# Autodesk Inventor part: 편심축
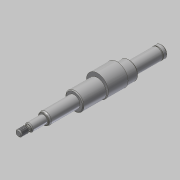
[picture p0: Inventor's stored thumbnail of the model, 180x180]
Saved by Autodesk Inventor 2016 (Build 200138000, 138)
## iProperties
Created: 2015-09
Part Number: 편심축
Material: 강철, 연강
Document SubType Name: Modeling
Designer: mduedu
Density: 1 g/cm^3
Appearance: 강철
Author: mduedu
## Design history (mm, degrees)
sketch "스케치1"
  geometry: L1 (-91, 0)-(91, 0); L2 (-91, 0)-(-91, 7.5); L3 (-91, 7.5)-(-49.85, 7.5); L4 (-49.85, 7.5)-(-49.85, 11.5); L5 (-49.85, 11.5)-(20.15, 11.5); L6 (20.15, 11.5)-(20.15, 7.5); L7 (20.15, 7.5)-(59.15, 7.5); L8 (59.15, 7.5)-(59.15, 5); L9 (59.15, 5)-(78.15, 5); L10 (78.15, 5)-(78.15, 3); L11 (78.15, 3)-(80.15, 3); L12 (81.882, 4)-(91, 4); L13 (91, 4)-(91, 0); L14 (80.15, 3)-(81.882, 4); 2 further points
  constraints: 28 end point, 9 parallel, 2 perpendicular, 1 coincident, 1 collinear, 1 horizontal, 1 midpoint
  dimensions: "d0" = 41.15 distance of L2.end L3.end; "d2" = 70 distance of L4.end L5.end; "d3" = 39 distance of L6.end L7.end; "d4" = 182 distance of L1.start L1.end; "d5" = 19 distance of L8.end L9.end; "d7" = 8 diameter of L12 L1; "d8" = 6 diameter of L11 L1; "d9" = 10 diameter of L9 L1; "d10" = 15 diameter of L7 L1; "d11" = 23 diameter of L5 L1; "d12" = 15 diameter of L3 L1; "d40" = 30 deg angle of L14 L12; "d41" = 2 distance of L10.end L11.end; "d42" = 3.73205 horizontal distance of L12.start L10.end (derived)
revolve "회전1" sketch "스케치1" stored, may be unused: angle "d13" = 90 deg
fillet "모깎기1" dims "d43" = 0.6
sketch "스케치2"
  geometry: L1 (-91, 7.5)-(-49.85, 7.5) reference; L2 (-91, -7.5)-(-91, 7.5) reference; L3 (91, -4)-(91, 4) reference; L4 (-91, 0)-(91, 0); L5 (-86, 7.5)-(-84.85, 7.5); L6 (-84.85, 7.5)-(-84.85, 7.15); L7 (-84.85, 7.15)-(-86, 7.15); L8 (-86, 7.15)-(-86, 7.5); 1 further point
  constraints: 10 end point, 2 midpoint, 2 parallel, 1 horizontal, 1 perpendicular, 1 point on line
  dimensions: "d14" = 5 distance between parallel lines of L8 L2; "d15" = 14.3 diameter of L7 L4; "d16" = 1.15 distance of L6.end L7.end
revolve "회전2" sketch "스케치2" stored, may be unused: angle "d17" = 90 deg
node "작업 평면1"
sketch "스케치3"
  geometry: C1 r 11.5 at (0, 0) reference; C2 r 14 at (0, 2.5); 1 further point
  constraints: 1 centre point, 1 tangent, 1 vertical alignment
  dimensions: "d19" = 28 diameter of C2
extrude "돌출1" join sketch "스케치3" distance "d21" = 25; taper "d22" = 0 deg
node "작업 평면2"
sketch "스케치4"
  geometry: L1 (9.5, 7.5)-(9.5, -7.5) reference; L2 (-9.5, 5)-(-9.5, -5) reference; L3 (9.5, 0)-(-9.5, 0); L4 (-5, -1.5)-(4, -1.5); L5 (4, 1.5)-(-5, 1.5); A1 r 1.5 centre (4, 0) between (4, -1.5) and (4, 1.5); A2 r 1.5 centre (-5, 0) between (-5, 1.5) and (-5, -1.5); 1 further point
  constraints: 6 end point, 4 point on circle, 4 tangent, 2 centre point, 2 midpoint, 2 parallel, 1 point on line
  dimensions: "d23" = 3 distance between parallel lines of L5 L4; "d25" = 12 dimension on A2 A1; "d26" = 3 distance edge to line of A2 L2
extrude "돌출2" cut sketch "스케치4" distance "d27" = 1.8; taper "d28" = 0 deg
chamfer "모따기1" distance "d29" = 1; stored, may be unused: second distance "d30" = 2, angle "d31" = 45 deg
sketch "스케치5"
  geometry: L1 (80.289, 3.08)-(81.882, 4) reference; L2 (81.882, 4)-(91, 4) reference; L3 (91, 4)-(91, -4) reference; L4 (91, -4)-(81.882, -4) reference; L5 (81.882, -4)-(80.289, -3.08) reference; L6 (79.989, -3)-(78.75, -3) reference; L7 (78.15, -3.6)-(78.15, -5) reference; L8 (78.15, -5)-(75.15, -5) reference; L9 (75.15, -5)-(75.15, -3.2) reference; L10 (75.15, -3.2)-(63.15, -3.2) reference; L11 (63.15, -3.2)-(63.15, -5) reference; L12 (63.15, -5)-(59.15, -5) reference; L13 (59.15, -5)-(59.15, -7.5) reference; L14 (59.15, -7.5)-(20.15, -7.5) reference; L15 (20.15, -7.5)-(20.15, -10.5) reference; L16 (20.15, -10.5)-(19.15, -11.5) reference; L17 (19.15, -11.5)-(-9.35, -11.5) reference; L18 (-9.35, -11.5)-(-34.35, -11.5) reference; L19 (-34.35, -11.5)-(-48.85, -11.5) reference; L20 (-48.85, -11.5)-(-49.85, -10.5) reference; L21 (-49.85, -10.5)-(-49.85, -7.5) reference; L22 (-49.85, -7.5)-(-84.85, -7.5) reference; L23 (-84.85, -7.5)-(-84.85, -7.15) reference; L24 (-84.85, -7.15)-(-86, -7.15) reference; L25 (-86, -7.15)-(-86, -7.5) reference; L26 (-86, -7.5)-(-90, -7.5) reference; L27 (-90, -7.5)-(-91, -6.5) reference; L28 (-91, -6.5)-(-91, 6.5) reference; L29 (-91, 6.5)-(-90, 7.5) reference; L30 (-90, 7.5)-(-86, 7.5) reference; L31 (-86, 7.5)-(-86, 7.15) reference; L32 (-86, 7.15)-(-84.85, 7.15) reference; L33 (-84.85, 7.15)-(-84.85, 7.5) reference; L34 (-84.85, 7.5)-(-49.85, 7.5) reference; L35 (-49.85, 7.5)-(-49.85, 10.5) reference; L36 (-49.85, 10.5)-(-48.85, 11.5) reference; L37 (-48.85, 11.5)-(-34.35, 11.5) reference; L38 (-34.35, 11.5)-(-34.35, 16.5) reference; L39 (-34.35, 16.5)-(-9.35, 16.5) reference; L40 (-9.35, 16.5)-(-9.35, 11.5) reference; L41 (-9.35, 11.5)-(19.15, 11.5) reference; L42 (19.15, 11.5)-(20.15, 10.5) reference; L43 (20.15, 10.5)-(20.15, 7.5) reference; L44 (20.15, 7.5)-(59.15, 7.5) reference; L45 (59.15, 7.5)-(59.15, 5) reference; L46 (59.15, 5)-(78.15, 5) reference; L47 (78.15, 5)-(78.15, 3.6) reference; L48 (78.75, 3)-(79.989, 3) reference; L49 (0, 0)-(91, 0); L50 (59.15, -6.55)-(57.505, -7.5); L51 (57.505, -7.5)-(59.15, -7.5); L52 (59.15, -7.5)-(59.15, -6.55); A1 r 0.6 centre (79.989, 3.6) between (79.989, 3) and (80.289, 3.08) reference; A2 r 0.6 centre (79.989, -3.6) between (80.289, -3.08) and (79.989, -3) reference; A3 r 0.6 centre (78.75, -3.6) between (78.75, -3) and (78.15, -3.6) reference; A4 r 0.6 centre (78.75, 3.6) between (78.15, 3.6) and (78.75, 3) reference
  constraints: 8 end point, 2 point on line, 1 midpoint, 1 parallel, 1 perpendicular
  dimensions: "d44" = 30 deg angle of L50 L51; "d45" = 13.1 diameter of L50.start L49
revolve "회전3" sketch "스케치5" stored, may be unused: angle "d46" = 90 deg
fillet "모깎기2" dims "d47" = 4, "d48" = 0.5
feature "스레드1" dims "d32" = 10, "d33" = 0
chamfer "모따기2" distance "d34" = 1; stored, may be unused: second distance "d35" = 2, angle "d36" = 45 deg
chamfer "모따기3" distance "d37" = 1; stored, may be unused: second distance "d38" = 2, angle "d39" = 45 deg
node "솔리드1"
node "절단 모서리 투영1"
other parameters: "d18" = -29.5
